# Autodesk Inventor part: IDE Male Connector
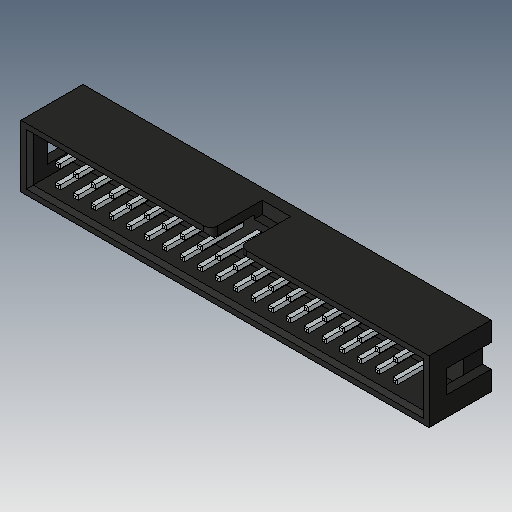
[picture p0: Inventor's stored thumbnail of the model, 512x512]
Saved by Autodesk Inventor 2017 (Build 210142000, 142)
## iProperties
Created: 2005-12
Part Number: IDE Male Connector
Material: Generic
Document SubType Name: Modeling
Designer: DanielSeverino
Density: 1 g/cm^3
Appearance: Default
Author: DanielSeverino
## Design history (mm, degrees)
feature "Solid1"
body "Solid2"
